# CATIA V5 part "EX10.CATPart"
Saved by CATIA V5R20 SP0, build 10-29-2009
Part number: EX10
Bounding box of the stored display mesh (mm): x -131.091 to 68.909, y 0 to 177.437, z 0 to 10
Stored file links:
  E:\Nouveau dossier\tarek\mécaniquee\Catia\TP 0\EX10.CATPart
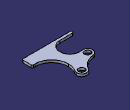
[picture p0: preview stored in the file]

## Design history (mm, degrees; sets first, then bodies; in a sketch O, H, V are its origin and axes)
Set1
  DatumSurface1 to DatumSurface21
Body1 (main body)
